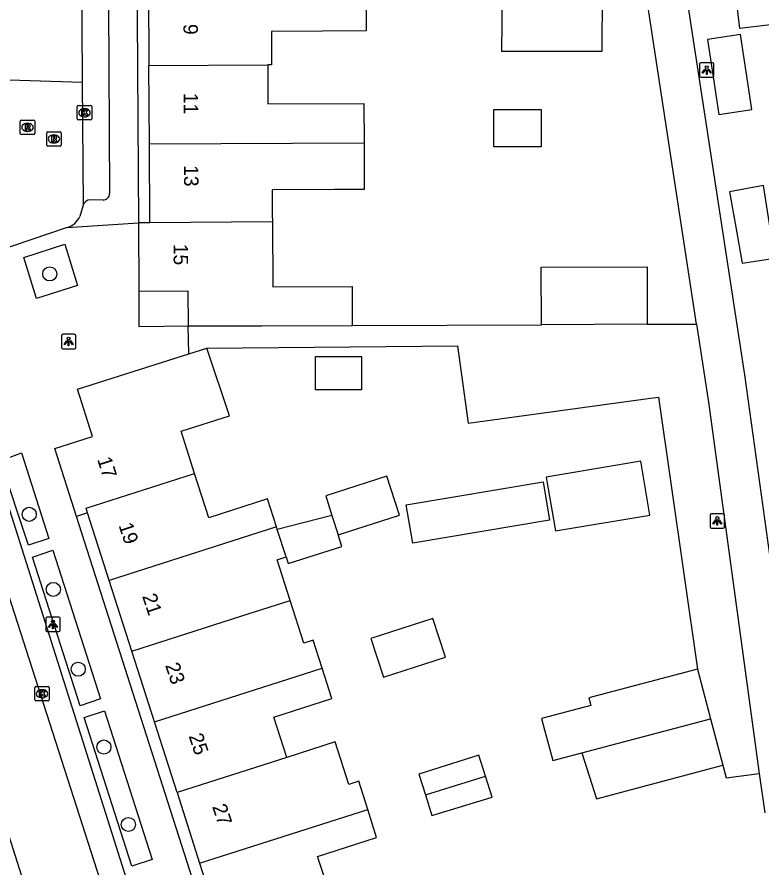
# Model space of a CAD drawing. Extents: x 159718 to 160783, y 383290 to 384030.
# Drawn here: x 160144.9 to 160196.6, y 383640.6 to 383699.6 of the extents above; entities that cross this region are included whole.
import ezdxf

# ---------------------------------------------------------------- set-up
doc = ezdxf.new("R2010")
doc.units = 0
for name, color, linetype in [('IMGEO_Boom', 7, 'Continuous'), ('IMGEO_Kolk', 7, 'Continuous'), ('IMGEO_Lichtpunt', 7, 'Continuous'), ('IMGEO_Pand', 7, 'Continuous'), ('IMGEO_Pand_nummerreeks', 7, 'Continuous'), ('IMGEO_Rijbaan_lokaal_open', 7, 'Continuous'), ('IMGEO_Rioolput', 7, 'Continuous'), ('IMGEO_Voetpad_open', 7, 'Continuous')]:
    doc.layers.add(name, color=color, linetype=linetype)

msp = doc.modelspace()

# ---------------------------------------------------------------- linework, layer by layer
at = {"layer": 'IMGEO_Boom'}
for centre in [(160147.197, 383681.743), (160145.776, 383665.073), (160147.447, 383659.869), (160149.174, 383654.332), (160150.953, 383648.937), (160152.65, 383643.566)]:
    msp.add_circle(centre, 0.489, dxfattribs=at)
at = {"layer": 'IMGEO_Kolk'}
for p, q in [((160149.109, 383692.492), (160149.109, 383693.344)), ((160149.184, 383693.418), (160150.036, 383693.418)), ((160150.11, 383693.344), (160150.11, 383692.492)), ((160149.597, 383693.198), (160149.622, 383693.198)), ((160150.036, 383692.418), (160149.184, 383692.418)), ((160149.62, 383692.638), (160149.595, 383692.638)), ((160146.162, 383652.205), (160146.162, 383653.057)), ((160146.237, 383653.131), (160147.089, 383653.131)), ((160146.65, 383652.911), (160146.675, 383652.911)), ((160147.163, 383653.057), (160147.163, 383652.205)), ((160147.089, 383652.131), (160146.237, 383652.131)), ((160146.673, 383652.351), (160146.648, 383652.351))]:
    msp.add_line(p, q, dxfattribs=at)
for points in [[(160149.109, 383692.492), (160149.109, 383693.344)], [(160149.184, 383693.418), (160150.036, 383693.418)], [(160150.11, 383693.344), (160150.11, 383692.492)], [(160149.43, 383693.118), (160149.553, 383693.118), (160149.553, 383692.967), (160149.683, 383693.118), (160149.847, 383693.118), (160149.701, 383692.967), (160149.854, 383692.718), (160149.702, 383692.718), (160149.617, 383692.882), (160149.553, 383692.815), (160149.553, 383692.718), (160149.43, 383692.718), (160149.43, 383693.118)], [(160150.036, 383692.418), (160149.184, 383692.418)], [(160146.162, 383652.205), (160146.162, 383653.057)], [(160146.237, 383653.131), (160147.089, 383653.131)], [(160146.483, 383652.831), (160146.606, 383652.831), (160146.606, 383652.68), (160146.736, 383652.831), (160146.9, 383652.831), (160146.754, 383652.68), (160146.907, 383652.431), (160146.755, 383652.431), (160146.67, 383652.595), (160146.606, 383652.528), (160146.606, 383652.431), (160146.483, 383652.431), (160146.483, 383652.831)], [(160147.163, 383653.057), (160147.163, 383652.205)], [(160147.089, 383652.131), (160146.237, 383652.131)]]:
    msp.add_lwpolyline(points, dxfattribs=at)
for centre, start, end in [((160149.186, 383693.342), 91.55205, 178.44795), ((160149.186, 383693.342), 91.55205, 178.44795), ((160150.034, 383693.342), 1.55205, 88.44795), ((160150.034, 383693.342), 1.55205, 88.44795), ((160149.186, 383692.494), 181.55205, 268.44795), ((160149.186, 383692.494), 181.55205, 268.44795), ((160150.034, 383692.494), 271.55205, 358.44795), ((160150.034, 383692.494), 271.55205, 358.44795), ((160146.239, 383653.055), 91.55205, 178.44795), ((160146.239, 383653.055), 91.55205, 178.44795), ((160147.087, 383653.055), 1.55205, 88.44795), ((160147.087, 383653.055), 1.55205, 88.44795), ((160146.239, 383652.207), 181.55205, 268.44795), ((160146.239, 383652.207), 181.55205, 268.44795), ((160147.087, 383652.207), 271.55205, 358.44795), ((160147.087, 383652.207), 271.55205, 358.44795)]:
    msp.add_arc(centre, 0.0765, start, end, dxfattribs=at)
for centre, major_axis, ratio, start_param, end_param in [((160149.596, 383692.918), (-0.387, 0.002), 0.722429, 4.712389, 7.853982), ((160149.621, 383692.918), (-0.39, 0.002), 0.717154, 1.570796, 4.712389), ((160146.649, 383652.631), (-0.387, 0.002), 0.722429, 4.712389, 7.853982), ((160146.674, 383652.631), (-0.39, 0.002), 0.717154, 1.570796, 4.712389)]:
    msp.add_ellipse(centre, major_axis=major_axis, ratio=ratio, start_param=start_param, end_param=end_param, dxfattribs=at)
at = {"layer": 'IMGEO_Lichtpunt'}
for p, q in [((160192.264, 383696.286), (160192.264, 383695.479)), ((160192.264, 383696.286), (160192.264, 383695.479)), ((160193.166, 383696.381), (160192.358, 383696.381)), ((160193.166, 383696.381), (160192.358, 383696.381)), ((160193.26, 383695.479), (160193.26, 383696.286)), ((160193.26, 383695.479), (160193.26, 383696.286)), ((160192.358, 383695.385), (160193.166, 383695.385)), ((160192.358, 383695.385), (160193.166, 383695.385)), ((160148.007, 383677.46), (160148.007, 383676.653)), ((160148.007, 383677.46), (160148.007, 383676.653)), ((160148.909, 383677.555), (160148.101, 383677.555)), ((160148.909, 383677.555), (160148.101, 383677.555)), ((160149.003, 383676.653), (160149.003, 383677.46)), ((160149.003, 383676.653), (160149.003, 383677.46)), ((160148.101, 383676.559), (160148.909, 383676.559)), ((160148.101, 383676.559), (160148.909, 383676.559)), ((160192.997, 383665.019), (160192.997, 383664.212)), ((160192.997, 383665.019), (160192.997, 383664.212)), ((160193.899, 383665.114), (160193.091, 383665.114)), ((160193.899, 383665.114), (160193.091, 383665.114)), ((160193.993, 383664.212), (160193.993, 383665.019)), ((160193.993, 383664.212), (160193.993, 383665.019)), ((160193.091, 383664.118), (160193.899, 383664.118)), ((160193.091, 383664.118), (160193.899, 383664.118)), ((160147.821, 383657.938), (160147.013, 383657.938)), ((160147.821, 383657.938), (160147.013, 383657.938)), ((160146.919, 383657.843), (160146.919, 383657.036)), ((160146.919, 383657.843), (160146.919, 383657.036)), ((160147.915, 383657.036), (160147.915, 383657.843)), ((160147.915, 383657.036), (160147.915, 383657.843)), ((160147.013, 383656.942), (160147.821, 383656.942)), ((160147.013, 383656.942), (160147.821, 383656.942))]:
    msp.add_line(p, q, dxfattribs=at)
for points in [[(160192.638, 383695.95), (160192.677, 383695.922), (160192.489, 383695.66), (160192.451, 383695.687), (160192.638, 383695.95)], [(160192.74, 383695.902), (160192.787, 383695.902), (160192.787, 383695.58), (160192.74, 383695.58), (160192.74, 383695.902)], [(160192.85, 383695.922), (160192.888, 383695.949), (160193.075, 383695.687), (160193.036, 383695.659), (160192.85, 383695.922)], [(160148.381, 383677.124), (160148.42, 383677.096), (160148.232, 383676.834), (160148.194, 383676.861), (160148.381, 383677.124)], [(160148.483, 383677.076), (160148.53, 383677.076), (160148.53, 383676.754), (160148.483, 383676.754), (160148.483, 383677.076)], [(160148.593, 383677.096), (160148.631, 383677.123), (160148.818, 383676.861), (160148.779, 383676.833), (160148.593, 383677.096)], [(160193.371, 383664.683), (160193.41, 383664.655), (160193.222, 383664.393), (160193.184, 383664.42), (160193.371, 383664.683)], [(160193.473, 383664.635), (160193.52, 383664.635), (160193.52, 383664.313), (160193.473, 383664.313), (160193.473, 383664.635)], [(160193.583, 383664.655), (160193.621, 383664.682), (160193.808, 383664.42), (160193.769, 383664.392), (160193.583, 383664.655)], [(160147.293, 383657.507), (160147.332, 383657.479), (160147.144, 383657.217), (160147.106, 383657.244), (160147.293, 383657.507)], [(160147.395, 383657.459), (160147.442, 383657.459), (160147.442, 383657.137), (160147.395, 383657.137), (160147.395, 383657.459)], [(160147.505, 383657.479), (160147.543, 383657.506), (160147.73, 383657.244), (160147.691, 383657.216), (160147.505, 383657.479)]]:
    msp.add_lwpolyline(points, dxfattribs=at)
for centre in [(160192.763, 383696.084), (160148.506, 383677.258), (160193.496, 383664.817), (160147.418, 383657.641)]:
    msp.add_circle(centre, 0.0994, dxfattribs=at)
for centre, start, end in [((160192.358, 383696.286), 90, 180), ((160192.358, 383696.286), 90, 180), ((160193.166, 383696.286), 0, 90), ((160193.166, 383696.286), 0, 90), ((160192.358, 383695.479), 180, 270), ((160192.358, 383695.479), 180, 270), ((160193.166, 383695.479), 270, 0), ((160193.166, 383695.479), 270, 360), ((160148.101, 383677.46), 90, 180), ((160148.101, 383677.46), 90, 180), ((160148.909, 383677.46), 0, 90), ((160148.909, 383677.46), 0, 90), ((160148.101, 383676.653), 180, 270), ((160148.101, 383676.653), 180, 270), ((160148.909, 383676.653), 270, 0), ((160148.909, 383676.653), 270, 360), ((160193.091, 383665.019), 90, 180), ((160193.091, 383665.019), 90, 180), ((160193.899, 383665.019), 0, 90), ((160193.899, 383665.019), 0, 90), ((160193.091, 383664.212), 180, 270), ((160193.091, 383664.212), 180, 270), ((160193.899, 383664.212), 270, 0), ((160193.899, 383664.212), 270, 360), ((160147.013, 383657.843), 90, 180), ((160147.013, 383657.843), 90, 180), ((160147.821, 383657.843), 0, 90), ((160147.821, 383657.843), 0, 90), ((160147.013, 383657.036), 180, 270), ((160147.013, 383657.036), 180, 270), ((160147.821, 383657.036), 270, 0), ((160147.821, 383657.036), 270, 360)]:
    msp.add_arc(centre, 0.0946, start, end, dxfattribs=at)
at = {"layer": 'IMGEO_Pand'}
for points in [[(160201.428, 383699.526), (160195.055, 383698.769), (160194.475, 383703.653), (160200.848, 383704.41), (160201.428, 383699.526)], [(160154.05, 383701.364), (160154.08, 383696.191)], [(160169.128, 383701.437), (160169.142, 383698.596), (160166.117, 383698.581), (160162.575, 383698.564), (160162.586, 383696.233), (160162.312, 383696.232)], [(160185.507, 383701.296), (160185.477, 383697.164), (160178.557, 383697.164), (160178.588, 383701.296), (160185.507, 383701.296)], [(160195.488, 383695.747), (160195.093, 383698.345), (160192.819, 383697.999), (160193.215, 383695.401), (160193.61, 383692.803), (160195.884, 383693.149), (160195.488, 383695.747)], [(160154.08, 383696.191), (160162.312, 383696.232)], [(160154.111, 383690.738), (160154.08, 383696.191)], [(160162.312, 383696.232), (160162.326, 383693.536), (160168.98, 383693.568), (160168.993, 383690.812)], [(160181.276, 383693.135), (160181.276, 383690.547), (160178.008, 383690.547), (160178.008, 383693.135), (160181.276, 383693.135)], [(160168.993, 383690.812), (160154.111, 383690.738)], [(160154.143, 383685.283), (160154.111, 383690.738)], [(160168.993, 383690.812), (160169.009, 383687.606), (160166.944, 383687.595), (160162.627, 383687.572), (160162.635, 383685.887), (160162.638, 383685.344)], [(160196.708, 383687.864), (160194.351, 383687.439), (160194.777, 383684.992), (160195.214, 383682.482), (160197.482, 383682.834), (160197.095, 383685.349), (160196.708, 383687.864)], [(160154.143, 383685.283), (160153.348, 383685.282)], [(160153.348, 383685.282), (160153.376, 383680.546)], [(160162.638, 383685.344), (160154.143, 383685.283)], [(160162.638, 383685.344), (160162.662, 383680.848), (160168.162, 383680.876), (160168.164, 383680.504), (160168.175, 383678.173)], [(160181.292, 383678.217), (160181.274, 383682.21), (160188.622, 383682.243), (160188.64, 383678.25)], [(160153.376, 383680.546), (160156.776, 383680.566), (160156.791, 383678.146)], [(160156.791, 383678.146), (160161.891, 383678.142), (160168.175, 383678.173)], [(160188.64, 383678.25), (160181.292, 383678.217)], [(160149.063, 383664.924), (160147.549, 383669.639), (160150.168, 383670.477), (160149.126, 383673.751), (160156.851, 383676.205)], [(160157.245, 383667.91), (160156.312, 383670.832), (160159.665, 383671.902), (160158.09, 383676.599)], [(160156.851, 383676.205), (160158.09, 383676.599)], [(160165.631, 383673.712), (160165.631, 383676.012), (160168.811, 383676.012), (160168.811, 383673.712), (160165.631, 383673.712)], [(160188.193, 383668.764), (160181.626, 383667.659), (160181.674, 383667.373), (160182.13, 383664.715), (160182.264, 383663.922), (160188.822, 383665.027), (160188.193, 383668.764)], [(160149.824, 383665.169), (160149.716, 383665.508), (160157.245, 383667.91)], [(160162.922, 383664.196), (160162.301, 383666.141), (160158.225, 383664.84), (160157.245, 383667.91)], [(160167.198, 383663.652), (160171.444, 383665.008), (160170.582, 383667.71), (160166.335, 383666.354), (160166.767, 383665.003)], [(160172.371, 383663.071), (160171.923, 383665.731), (160181.411, 383667.329), (160181.859, 383664.669), (160172.371, 383663.071)], [(160149.824, 383665.169), (160149.063, 383664.924)], [(160151.321, 383660.492), (160149.824, 383665.169)], [(160166.767, 383665.003), (160162.981, 383664.013)], [(160166.767, 383665.003), (160167.198, 383663.652)], [(160162.922, 383664.196), (160151.321, 383660.492)], [(160162.981, 383664.013), (160162.922, 383664.196)], [(160163.585, 383662.121), (160162.981, 383664.013)], [(160163.585, 383662.121), (160163.734, 383661.653), (160167.457, 383662.841), (160167.198, 383663.652)], [(160163.872, 383659.096), (160162.969, 383661.924), (160163.585, 383662.121)], [(160152.889, 383655.591), (160151.321, 383660.492)], [(160152.889, 383655.591), (160160.458, 383658.007), (160163.872, 383659.096)], [(160166.086, 383654.402), (160165.462, 383656.356), (160164.813, 383656.149), (160163.872, 383659.096)], [(160170.345, 383653.786), (160174.638, 383655.175), (160173.77, 383657.859), (160169.477, 383656.47), (160170.345, 383653.786)], [(160154.457, 383650.689), (160152.889, 383655.591)], [(160154.457, 383650.689), (160166.086, 383654.402)], [(160163.637, 383648.218), (160162.745, 383651.012), (160166.76, 383652.293), (160166.086, 383654.402)], [(160192.113, 383654.345), (160184.578, 383652.353), (160184.719, 383651.818), (160181.311, 383650.917), (160181.518, 383650.134), (160182.079, 383648.01), (160184.092, 383648.542)], [(160192.113, 383654.345), (160193.023, 383650.903)], [(160184.092, 383648.542), (160193.023, 383650.903)], [(160193.023, 383650.903), (160193.872, 383647.691)], [(160156.025, 383645.788), (160154.457, 383650.689)], [(160169.249, 383644.608), (160168.623, 383646.568), (160167.941, 383646.35), (160167.002, 383649.292), (160163.637, 383648.218)], [(160184.092, 383648.542), (160185.12, 383645.345), (160193.872, 383647.691)], [(160163.637, 383648.218), (160156.025, 383645.788)], [(160177.414, 383646.914), (160176.954, 383648.373), (160172.795, 383647.062), (160173.247, 383645.629)], [(160173.247, 383645.629), (160177.414, 383646.914)], [(160173.247, 383645.629), (160173.699, 383644.195), (160177.874, 383645.454), (160177.414, 383646.914)], [(160156.025, 383645.788), (160157.593, 383640.887)], [(160157.593, 383640.887), (160169.249, 383644.608)], [(160166.736, 383638.403), (160165.769, 383641.355), (160169.87, 383642.664), (160169.249, 383644.608)], [(160157.593, 383640.887), (160159.161, 383635.985)]]:
    msp.add_lwpolyline(points, dxfattribs=at)
at = {"layer": 'IMGEO_Rijbaan_lokaal_open'}
for points in [[(160151.011, 383741.937), (160151.045, 383740.445), (160151.099, 383735.432), (160151.342, 383687.314)], [(160153.157, 383717.414), (160153.348, 383685.282)], [(160149.329, 383715.274), (160149.458, 383695.025)], [(160149.458, 383695.025), (160144.401, 383695.175)], [(160149.458, 383695.025), (160149.512, 383686.502)], [(160150.893, 383686.864), (160149.998, 383686.878)], [(160149.512, 383686.502), (160149.291, 383685.721)], [(160148.407, 383684.961), (160153.348, 383685.282)], [(160148.407, 383684.961), (160142.197, 383682.858)], [(160146.289, 383680.045), (160145.407, 383682.871), (160148.248, 383683.796), (160149.131, 383680.937), (160146.289, 383680.045)], [(160153.376, 383680.546), (160153.387, 383678.102), (160156.791, 383678.146)], [(160156.851, 383676.205), (160156.791, 383678.146)], [(160145.734, 383662.939), (160143.781, 383668.791), (160145.234, 383669.335), (160147.143, 383663.407), (160145.734, 383662.939)], [(160156.009, 383623.174), (160141.47, 383668.37)], [(160143.499, 383668.167), (160153.963, 383635.229), (160166.59, 383596.057)], [(160169.432, 383601.256), (160149.063, 383664.924)], [(160150.728, 383652.269), (160149.311, 383651.799), (160146.002, 383662.1), (160147.403, 383662.598), (160150.728, 383652.269)], [(160141.576, 383651.473), (160148.415, 383629.989), (160151.141, 383621.545)], [(160152.886, 383640.673), (160149.585, 383650.975), (160150.993, 383651.448), (160154.312, 383641.139), (160152.886, 383640.673)]]:
    msp.add_lwpolyline(points, dxfattribs=at)
for centre, radius, start, end in [((160149.994, 383686.381), 0.497, 89.58687, 165.86868), ((160150.9, 383687.306), 0.442, 269.12878, 0.99869), ((160147.986, 383686.345), 1.446, 286.91678, 334.45639)]:
    msp.add_arc(centre, radius, start, end, dxfattribs=at)
at = {"layer": 'IMGEO_Rioolput'}
for p, q in [((160145.154, 383691.482), (160145.154, 383692.334)), ((160145.229, 383692.408), (160146.081, 383692.408)), ((160145.642, 383692.188), (160145.667, 383692.188)), ((160146.155, 383692.334), (160146.155, 383691.482)), ((160145.665, 383691.628), (160145.64, 383691.628)), ((160147.063, 383691.606), (160147.915, 383691.606)), ((160146.081, 383691.408), (160145.229, 383691.408)), ((160146.988, 383690.68), (160146.988, 383691.532)), ((160147.476, 383691.386), (160147.501, 383691.386)), ((160147.989, 383691.532), (160147.989, 383690.68)), ((160147.915, 383690.606), (160147.063, 383690.606)), ((160147.499, 383690.826), (160147.474, 383690.826))]:
    msp.add_line(p, q, dxfattribs=at)
for points in [[(160145.154, 383691.482), (160145.154, 383692.334)], [(160145.229, 383692.408), (160146.081, 383692.408)], [(160146.155, 383692.334), (160146.155, 383691.482)], [(160145.743, 383692.106), (160145.491, 383692.108), (160145.491, 383691.708)], [(160145.491, 383691.708), (160145.615, 383691.708), (160145.615, 383691.87), (160145.626, 383691.87)], [(160145.669, 383692.027), (160145.615, 383692.027), (160145.615, 383691.946)], [(160145.615, 383691.946), (160145.667, 383691.946)], [(160145.673, 383691.841), (160145.744, 383691.708), (160145.884, 383691.708), (160145.819, 383691.834)], [(160147.063, 383691.606), (160147.915, 383691.606)], [(160146.081, 383691.408), (160145.229, 383691.408)], [(160146.988, 383690.68), (160146.988, 383691.532)], [(160147.577, 383691.304), (160147.325, 383691.306), (160147.325, 383690.906)], [(160147.325, 383690.906), (160147.449, 383690.906), (160147.449, 383691.068), (160147.46, 383691.068)], [(160147.503, 383691.225), (160147.449, 383691.225), (160147.449, 383691.144)], [(160147.449, 383691.144), (160147.501, 383691.144)], [(160147.507, 383691.039), (160147.578, 383690.906), (160147.718, 383690.906), (160147.653, 383691.032)], [(160147.989, 383691.532), (160147.989, 383690.68)], [(160147.915, 383690.606), (160147.063, 383690.606)]]:
    msp.add_lwpolyline(points, dxfattribs=at)
for centre, radius, start, end in [((160145.231, 383692.332), 0.0765, 91.55205, 178.44795), ((160145.231, 383692.332), 0.0765, 91.55205, 178.44795), ((160146.079, 383692.332), 0.0765, 1.55205, 88.44795), ((160146.079, 383692.332), 0.0765, 1.55205, 88.44795), ((160145.625, 383691.817), 0.0533, 26.02933, 88.69889), ((160145.651, 383692.135), 0.19, 274.7715, 282.96867), ((160145.675, 383691.931), 0.0964, 77.00612, 93.18647), ((160145.689, 383691.988), 0.0378, 276.66336, 79.67722), ((160145.742, 383691.996), 0.109, 350.36119, 89.41601), ((160145.74, 383691.996), 0.112, 277.58423, 350.98172), ((160145.724, 383691.781), 0.108, 29.51342, 73.79051), ((160147.065, 383691.53), 0.0765, 91.55205, 178.44795), ((160147.065, 383691.53), 0.0765, 91.55205, 178.44795), ((160147.913, 383691.53), 0.0765, 1.55205, 88.44795), ((160147.913, 383691.53), 0.0765, 1.55205, 88.44795), ((160145.231, 383691.484), 0.0765, 181.55205, 268.44795), ((160145.231, 383691.484), 0.0765, 181.55205, 268.44795), ((160146.079, 383691.484), 0.0765, 271.55205, 358.44795), ((160146.079, 383691.484), 0.0765, 271.55205, 358.44795), ((160147.459, 383691.015), 0.0533, 26.02933, 88.69889), ((160147.485, 383691.333), 0.19, 274.7715, 282.96867), ((160147.509, 383691.129), 0.0964, 77.00612, 93.18647), ((160147.523, 383691.186), 0.0378, 276.66336, 79.67722), ((160147.576, 383691.194), 0.109, 350.36119, 89.41601), ((160147.574, 383691.194), 0.112, 277.58423, 350.98172), ((160147.558, 383690.979), 0.108, 29.51342, 73.79051), ((160147.065, 383690.682), 0.0765, 181.55205, 268.44795), ((160147.065, 383690.682), 0.0765, 181.55205, 268.44795), ((160147.913, 383690.682), 0.0765, 271.55205, 358.44795), ((160147.913, 383690.682), 0.0765, 271.55205, 358.44795)]:
    msp.add_arc(centre, radius, start, end, dxfattribs=at)
for centre, major_axis, ratio, start_param, end_param in [((160145.641, 383691.908), (-0.387, 0.002), 0.722429, 4.712389, 7.853982), ((160145.666, 383691.908), (-0.39, 0.002), 0.717154, 1.570796, 4.712389), ((160147.475, 383691.106), (-0.387, 0.002), 0.722429, 4.712389, 7.853982), ((160147.5, 383691.106), (-0.39, 0.002), 0.717154, 1.570796, 4.712389)]:
    msp.add_ellipse(centre, major_axis=major_axis, ratio=ratio, start_param=start_param, end_param=end_param, dxfattribs=at)
at = {"layer": 'IMGEO_Voetpad_open'}
for points in [[(160192.049, 383678.265), (160186.233, 383716.436)], [(160199.575, 383644.793), (160195.404, 383674.755), (160189.268, 383714.705)], [(160168.175, 383678.173), (160181.292, 383678.217)], [(160188.64, 383678.25), (160192.049, 383678.265)], [(160192.049, 383678.265), (160192.874, 383672.849), (160196.406, 383647.105)], [(160158.09, 383676.599), (160175.472, 383676.766), (160176.207, 383671.385), (160188.87, 383673.117), (160189.416, 383673.192), (160192.113, 383654.345)], [(160193.872, 383647.691), (160194.113, 383646.791), (160196.406, 383647.105)], [(160196.406, 383647.105), (160196.781, 383644.368)]]:
    msp.add_lwpolyline(points, dxfattribs=at)

# ---------------------------------------------------------------- texts
at = {"layer": 'IMGEO_Pand_nummerreeks'}
for s, rotation, p in [('9', 270.2347, (160156.469, 383699.075)), ('11', 270.2347, (160156.489, 383694.298)), ('13', 270.2347, (160156.509, 383689.288)), ('15', 270.22897, (160155.787, 383683.834)), ('17', 287.70991, (160150.477, 383668.892)), ('19', 288.40892, (160151.96, 383664.319)), ('21', 288.40892, (160153.597, 383659.398)), ('23', 288.40892, (160155.192, 383654.606)), ('25', 288.40892, (160156.823, 383649.706)), ('27', 288.40892, (160158.453, 383644.807))]:
    msp.add_text(s, height=1, rotation=rotation, dxfattribs=at).set_placement(p)

doc.saveas('drawing.dxf')
